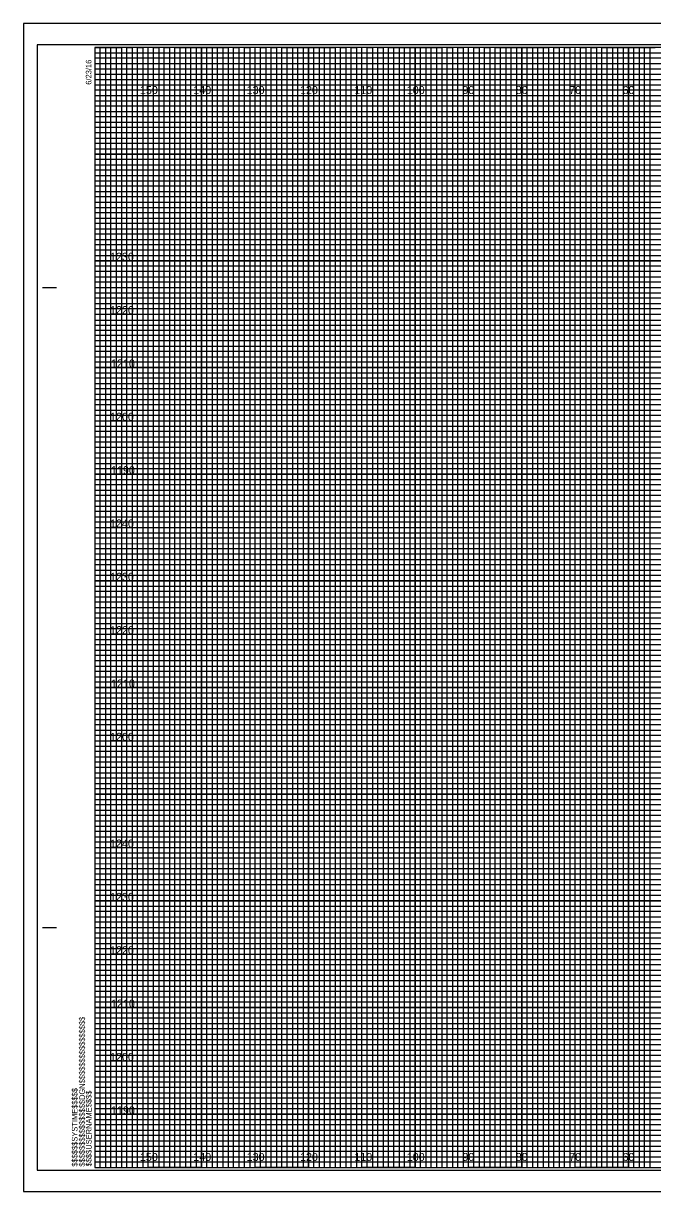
# Model space of a CAD drawing. Extents: x -13 to 323, y 156 to 434.
# Drawn here: x -13.4 to 104.5, y 215.5 to 434.5 of the extents above; entities that cross this region are included whole.
import ezdxf

# ---------------------------------------------------------------- set-up
doc = ezdxf.new("R2010")
doc.units = 0
for name, color, linetype in [('Prop XS Elevation Labels', 7, 'Continuous'), ('Prop XS Offset Labels', 7, 'Continuous'), ('Sheet Cross Section CELL', 7, 'Continuous'), ('Sheet Cross Section Grid Major CELL', 7, 'Continuous'), ('Sheet Cross Section Grid Middle CELL', 7, 'Continuous'), ('Sheet Cross Section Grid Minor 1 CELL', 7, 'Continuous'), ('Sheet Cross Section Grid Minor 2 CELL', 7, 'Continuous'), ('Sheet Cutting Line CELL', 7, 'Continuous'), ('Sheet DOT Grid CELL', 7, 'Continuous'), ('Sheet Plot Border Inside CELL', 7, 'Continuous'), ('Sheet Plot Border Outside CELL', 7, 'Continuous')]:
    doc.layers.add(name, color=color, linetype=linetype)

msp = doc.modelspace()

# ---------------------------------------------------------------- linework, layer by layer
at = {"layer": 'Sheet Cross Section CELL'}
for p, q in [((-9.8, 385), (-7.3, 385)), ((-9.7, 385), (-7.2, 385)), ((-9.8, 265), (-7.3, 265)), ((-9.7, 265), (-7.2, 265)), ((0, 220), (0, 220)), ((0, 220), (0, 220)), ((0, 220), (0, 220)), ((0, 220), (0, 220)), ((0, 220), (0, 220)), ((0, 220), (0, 220)), ((0, 220), (0, 220))]:
    msp.add_line(p, q, dxfattribs=at)
msp.add_lwpolyline([(320, 430), (0, 430), (0, 220), (320, 220)], close=True, dxfattribs=at)
at = {"layer": 'Sheet Cross Section Grid Major CELL'}
for p, q in [((10, 430), (0, 430)), ((10, 220), (10, 430)), ((30, 430), (20, 430)), ((20, 430), (20, 220)), ((30, 220), (30, 430)), ((50, 430), (40, 430)), ((40, 430), (40, 220)), ((50, 220), (50, 430)), ((70, 430), (60, 430)), ((60, 430), (60, 220)), ((70, 220), (70, 430)), ((90, 430), (80, 430)), ((80, 430), (80, 220)), ((90, 220), (90, 430)), ((110, 430), (100, 430)), ((100, 430), (100, 220)), ((20, 220), (10, 220)), ((40, 220), (30, 220)), ((60, 220), (50, 220)), ((80, 220), (70, 220)), ((100, 220), (90, 220))]:
    msp.add_line(p, q, dxfattribs=at)
for points in [[(0, 420), (320, 420), (320, 410), (0, 410)], [(0, 400), (320, 400), (320, 390), (0, 390)], [(0, 380), (320, 380), (320, 370), (0, 370)], [(0, 360), (320, 360), (320, 350), (0, 350)], [(0, 340), (320, 340), (320, 330), (0, 330)], [(0, 320), (320, 320), (320, 310), (0, 310)], [(0, 300), (320, 300), (320, 290), (0, 290)], [(0, 280), (320, 280), (320, 270), (0, 270)], [(0, 260), (320, 260), (320, 250), (0, 250)], [(0, 240), (320, 240), (320, 230), (0, 230)]]:
    msp.add_lwpolyline(points, dxfattribs=at)
at = {"layer": 'Sheet Cross Section Grid Middle CELL'}
for points in [[(0, 430), (5, 430), (5, 220), (15, 220), (15, 430), (25, 430), (25, 220), (35, 220), (35, 430), (45, 430), (45, 220), (55, 220), (55, 430), (65, 430), (65, 220), (75, 220), (75, 430), (85, 430), (85, 220), (95, 220), (95, 430), (105, 430)], [(0, 425), (275, 425)], [(0, 405), (320, 405), (320, 415), (0, 415)], [(0, 385), (320, 385), (320, 395), (0, 395)], [(0, 365), (320, 365), (320, 375), (0, 375)], [(0, 345), (320, 345), (320, 355), (0, 355)], [(0, 325), (320, 325), (320, 335), (0, 335)], [(0, 305), (320, 305), (320, 315), (0, 315)], [(0, 285), (320, 285), (320, 295), (0, 295)], [(0, 265), (320, 265), (320, 275), (0, 275)], [(0, 245), (320, 245), (320, 255), (0, 255)], [(0, 225), (320, 225), (320, 235), (0, 235)]]:
    msp.add_lwpolyline(points, dxfattribs=at)
at = {"layer": 'Sheet Cross Section Grid Minor 1 CELL'}
for p, q in [((0, 429), (260, 429)), ((260, 427.98), (0, 427.98)), ((0, 427.98), (0, 427)), ((0, 427), (260, 427)), ((260, 425.89), (0, 425.89)), ((0, 425.89), (0, 424)), ((0, 424), (320, 424))]:
    msp.add_line(p, q, dxfattribs=at)
for points in [[(0, 423), (270, 423), (320, 423), (320, 422), (0, 422)], [(0, 421), (320, 421), (320, 419), (0, 419)], [(0, 418), (320, 418), (320, 417), (0, 416.98)], [(0, 416), (320, 416), (320, 414), (0, 414)], [(0, 413), (320, 413), (320, 412), (0, 412)], [(0, 411), (320, 411), (320, 409), (0, 409)], [(0, 408), (320, 408), (320, 407), (0, 407)], [(0, 406), (320, 406), (320, 404), (0, 404)], [(0, 403), (320, 403), (320, 402), (0, 402)], [(0, 401), (320, 401), (320, 399), (0, 399)], [(0, 398), (320, 398), (320, 397), (0, 397)], [(0, 396), (320, 396), (320, 393.95), (320, 393), (320, 392), (0, 392)], [(0, 394), (320, 394), (320, 393), (0, 393)], [(0, 391), (320, 391), (320, 389), (0, 389.03)], [(0, 389.03), (320, 389), (320, 388), (0, 388)], [(0, 387), (320, 387), (320, 386), (0, 386)], [(0, 384), (320, 384), (320, 383), (0, 383)], [(0, 382), (320, 382), (320, 381), (0, 381)], [(-0.07, 378.89), (320, 378.89), (320, 377.88), (-0.07, 377.88)], [(0, 377), (320, 377), (320, 376), (0, 376)], [(0, 374), (320, 374), (320, 373), (0, 373)], [(0, 372), (320, 372), (320, 371), (0, 371)], [(0, 369), (320, 369), (320, 368), (0, 368)], [(0, 367), (320, 367), (320, 366), (0, 366)], [(0, 364), (320, 364), (320, 363), (0, 363)], [(0, 362), (320, 362), (320, 361), (0, 361)], [(0, 359), (320, 359), (319.99, 357.98), (0, 358)], [(0, 357), (320, 357), (320, 356), (0, 356)], [(0, 354), (320, 354), (320, 353), (0, 353)], [(0, 352), (320, 352), (320, 351), (0, 351)], [(0, 349), (320, 349), (320, 348), (0, 348)], [(0, 347), (320, 347), (320, 346), (0, 346)], [(0, 344), (320, 344), (320, 343), (0, 343)], [(0, 342), (320, 342), (320, 341), (0, 341)], [(0, 339), (320, 339), (320, 338), (0, 338)], [(0, 336.99), (320.07, 336.91), (320, 336), (0, 336)], [(0, 334), (320, 334), (320, 333), (0, 333)], [(0, 332), (320, 332), (320, 331), (0, 331)], [(0, 329), (320, 329), (320, 328), (0, 328)], [(0, 327), (320, 327), (320, 326), (0, 326)], [(0, 324), (320, 324), (320, 323), (0, 323)], [(0, 322), (320, 322), (320, 321), (0, 321)], [(0, 319), (320, 319), (320, 318), (0, 318)], [(0, 317), (320, 317), (320, 316), (0, 316)], [(0, 314), (320, 314), (320, 313), (0, 313)], [(0, 312), (320, 312), (320, 311), (0, 311)], [(0, 309), (320, 309), (320, 308), (0, 308)], [(0, 307), (320, 307), (320, 306), (0, 306)], [(0, 304), (320, 304), (320, 303), (0, 303)], [(0, 302), (320, 302), (320, 301), (0, 301)], [(0, 299), (320, 299), (319.99, 297.98), (0, 298)], [(0, 297), (320, 297), (320, 296), (0, 296)], [(0, 294), (320, 294), (320, 293), (0, 293)], [(0, 292), (320, 292), (320, 291), (0, 291)], [(0, 289), (320, 289), (320, 288), (0, 288)], [(0, 287), (320, 287), (320, 286), (0, 286)], [(0, 284), (320, 284), (320, 283), (0, 283)], [(0, 282), (320, 282), (320, 281), (0, 281)], [(0, 279), (320, 279), (320, 278), (0, 278)], [(0, 276.99), (320.07, 276.91), (320, 276), (0, 276)], [(0, 274), (320, 274), (320, 273), (0, 273)], [(0, 272), (320, 272), (320, 271), (0, 271)], [(0, 269), (320, 269), (320, 268), (0, 268)], [(0, 267), (320, 267), (320, 266), (0, 266)], [(0, 264), (320, 264), (320, 263), (0, 263)], [(0, 262), (320, 262), (320, 261), (0, 261)], [(0, 259), (320, 259), (320, 258), (0, 258)], [(0, 257), (320, 257), (320, 256), (0, 256)], [(0, 254), (320, 254), (320, 253), (0, 253)], [(0, 252), (320, 252), (320, 251), (0, 251)], [(0, 249), (320, 249), (320, 248), (0, 248)], [(0, 247), (320, 247), (320, 246), (0, 246)], [(0, 244), (320, 244), (320, 243), (0, 243)], [(0, 242), (320, 242), (320, 241), (0, 241)], [(0, 239), (320, 239), (320, 238), (0, 238)], [(0, 237), (320, 237), (320, 236), (0, 236)], [(0, 234), (320, 234), (320, 233), (0, 233)], [(0, 232), (320, 232), (320, 231), (0, 231)], [(0, 229), (320, 229), (320, 228), (0, 228)], [(0, 227), (320, 227), (320, 226), (0, 226)], [(0, 224), (320, 224), (320, 223), (0, 223)], [(0, 222), (320, 222), (320, 221), (0, 221)]]:
    msp.add_lwpolyline(points, dxfattribs=at)
at = {"layer": 'Sheet Cross Section Grid Minor 2 CELL'}
for points in [[(0, 220), (1, 220), (1, 430), (2, 430), (2, 220)], [(2, 220), (3, 220), (3, 430), (4, 430), (4, 220)], [(5, 220), (6, 220), (6, 430), (7, 430), (7, 220)], [(7, 220), (8, 220), (8, 430), (9, 430), (9, 220)], [(10, 220), (11, 220), (11, 430), (12, 430), (12, 220)], [(12, 220), (13, 220), (13, 430), (14, 430), (14, 220)], [(15, 220), (16, 220), (16, 430), (17, 430), (17, 220)], [(17, 220), (18, 220), (18, 430), (19, 430), (19, 220)], [(20, 220), (21, 220), (21, 430), (22, 430), (22, 220)], [(22, 220), (23, 220), (23, 430), (24, 430), (24, 220)], [(25, 220), (26, 220), (26, 430), (27, 430), (27, 220)], [(27, 220), (28, 220), (28, 430), (29, 430), (29, 220)], [(30, 220), (31, 220), (31, 430), (32, 430), (32, 220)], [(32, 220), (33, 220), (33, 430), (34, 430), (34, 220)], [(35, 220), (36, 220), (36, 430), (37, 430), (37, 220)], [(37, 220), (38, 220), (38, 430), (39, 430), (39, 220)], [(40, 220), (41, 220), (41, 430), (42, 430), (42, 220)], [(42, 220), (43, 220), (43, 430), (44, 430), (44, 220)], [(45, 220), (46, 220), (46, 430), (47, 430), (47, 220)], [(47, 220), (48, 220), (48, 430), (49, 430), (49, 220)], [(50, 220), (51, 220), (51, 430), (52, 430), (52, 220)], [(52, 220), (53, 220), (53, 430), (54, 430), (54, 220)], [(55, 220), (56, 220), (56, 430), (57, 430), (57, 220)], [(57, 220), (58, 220), (58, 430), (59, 430), (59, 220)], [(60, 220), (61, 220), (61, 430), (62, 430), (62, 220)], [(62, 220), (63, 220), (63, 430), (64, 430), (64, 220)], [(65, 220), (66, 220), (66, 430), (67, 430), (67, 220)], [(67, 220), (68, 220), (68, 430), (69, 430), (69, 220)], [(70, 220), (71, 220), (71, 430), (72, 430), (72, 220)], [(72, 220), (73, 220), (73, 430), (74, 430), (74, 220)], [(75, 220), (76, 220), (76, 430), (77, 430), (77, 220)], [(77, 220), (78, 220), (78, 430), (79, 430), (79, 220)], [(80, 220), (81, 220), (81, 430), (82, 430), (82, 220)], [(82, 220), (83, 220), (83, 430), (84, 430), (84, 220)], [(85, 220), (86, 220), (86, 430), (87, 430), (87, 220)], [(87, 220), (88, 220), (88, 430), (89, 430), (89, 220)], [(90, 220), (91, 220), (91, 430), (92, 430), (92, 220)], [(92, 220), (93, 220), (93, 430), (94, 430), (94, 220)], [(95, 220), (96, 220), (96, 430), (97, 430), (97, 220)], [(97, 220), (98, 220), (98, 430), (99, 430), (99, 220)], [(100, 220), (101, 220), (101, 430), (102, 430), (102, 220)], [(102, 220), (103, 220), (103, 430), (104, 430), (104, 220)]]:
    msp.add_lwpolyline(points, dxfattribs=at)
at = {"layer": 'Sheet Cutting Line CELL'}
for p, q in [((323.3, 434.5), (-13.4, 434.5)), ((-13.4, 434.5), (-13.4, 215.5)), ((-13.4, 215.5), (323.3, 215.5))]:
    msp.add_line(p, q, dxfattribs=at)
at = {"layer": 'Sheet DOT Grid CELL'}
for p, q in [((10, 220), (10, 430)), ((20, 220), (20, 430)), ((30, 220), (30, 430)), ((40, 220), (40, 430)), ((50, 220), (50, 430)), ((60, 220), (60, 430)), ((70, 220), (70, 430)), ((80, 220), (80, 430)), ((90, 220), (90, 430)), ((100, 220), (100, 430)), ((0, 420), (320, 420)), ((0, 410), (320, 410)), ((0, 400), (320, 400)), ((0, 390), (320, 390)), ((0, 380), (320, 380)), ((0, 370), (320, 370)), ((0, 360), (320, 360)), ((0, 350), (320, 350)), ((0, 340), (320, 340)), ((0, 330), (320, 330)), ((0, 320), (320, 320)), ((0, 310), (320, 310)), ((0, 300), (320, 300)), ((0, 290), (320, 290)), ((0, 280), (320, 280)), ((0, 270), (320, 270)), ((0, 260), (320, 260)), ((0, 250), (320, 250)), ((0, 240), (320, 240)), ((0, 230), (320, 230))]:
    msp.add_line(p, q, dxfattribs=at)
at = {"layer": 'Sheet Plot Border Inside CELL'}
msp.add_lwpolyline([(-10.8, 219.5), (322.4, 219.5), (322.4, 430.5), (-10.8, 430.5)], close=True, dxfattribs=at)
at = {"layer": 'Sheet Plot Border Outside CELL'}
msp.add_lwpolyline([(-13.4, 215.5), (323.3, 215.5), (323.3, 434.5), (-13.4, 434.5)], close=True, dxfattribs=at)

# ---------------------------------------------------------------- texts
at = {"layer": 'Prop XS Elevation Labels'}
for s, p in [('1230', (2.85, 390)), ('1220', (2.85, 380)), ('1210', (3.03, 370)), ('1200', (2.85, 360)), ('1190', (3.03, 350)), ('1240', (2.85, 340)), ('1230', (2.85, 330)), ('1220', (2.85, 320)), ('1210', (3.03, 310)), ('1200', (2.85, 300)), ('1240', (2.85, 280)), ('1230', (2.85, 270)), ('1220', (2.85, 260)), ('1210', (3.03, 250)), ('1200', (2.85, 240)), ('1190', (3.03, 230))]:
    msp.add_text(s, height=1.5, dxfattribs=at).set_placement(p)
at = {"layer": 'Prop XS Offset Labels'}
for s, p in [('150', (8.44, 421.25)), ('140', (18.44, 421.25)), ('130', (28.44, 421.25)), ('120', (38.44, 421.25)), ('110', (48.62, 421.25)), ('100', (58.44, 421.25)), ('90', (68.86, 421.25)), ('80', (78.86, 421.25)), ('70', (88.86, 421.25)), ('60', (98.86, 421.25)), ('150', (8.44, 221.25)), ('140', (18.44, 221.25)), ('130', (28.44, 221.25)), ('120', (38.44, 221.25)), ('110', (48.62, 221.25)), ('100', (58.44, 221.25)), ('90', (68.86, 221.25)), ('80', (78.86, 221.25)), ('70', (88.86, 221.25)), ('60', (98.86, 221.25))]:
    msp.add_text(s, height=1.5, dxfattribs=at).set_placement(p)
at = {"layer": 'Sheet Cross Section CELL'}
for s, p in [('6/23/16', (-0.65, 423)), ('$$$$$$$$$$$$$$$$DGN$$$$$$$$$$$$$$$$', (-1.88, 220.18)), ('$$$$$$SYSTIME$$$$$', (-3.26, 220.18)), ('$$$$USERNAME$$$$', (-0.62, 220.23))]:
    msp.add_text(s, height=1.05, rotation=90, dxfattribs=at).set_placement(p)

doc.saveas('drawing.dxf')
